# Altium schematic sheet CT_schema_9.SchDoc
size 226 x 144 mm
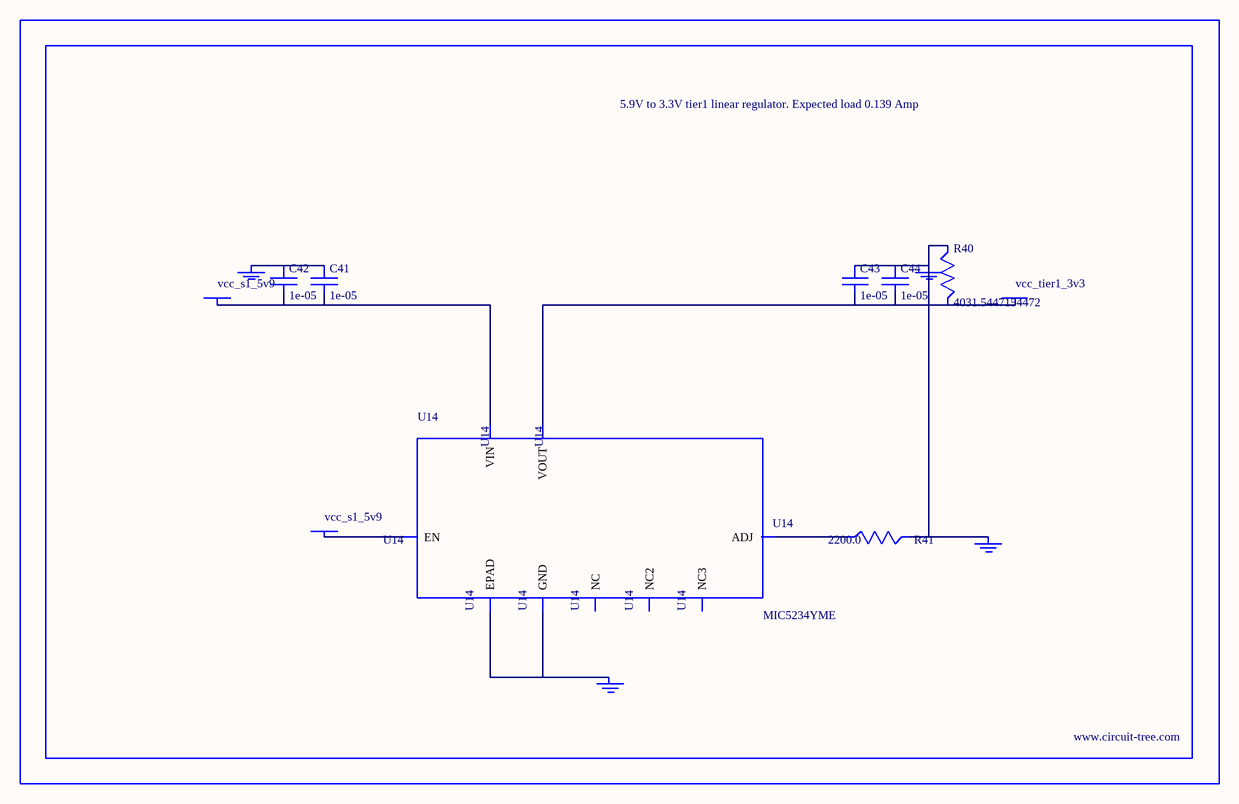
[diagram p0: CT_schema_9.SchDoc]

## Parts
BORDER8  (no value)
C41  1e-05  [C1210]
C42  1e-05  [C1210]
C43  1e-05  [C1210]
C44  1e-05  [C1210]
GND_INSTANCE_8_0  (no value)
GND_INSTANCE_8_1  (no value)
GND_INSTANCE_8_2  (no value)
GND_INSTANCE_8_3  (no value)
POWER_INSTANCE_8_0  vcc_tier1_3v3
POWER_INSTANCE_8_1  vcc_s1_5v9
POWER_INSTANCE_8_2  vcc_s1_5v9
R40  4031.5447154472  [R0603]
R41  2200.0  [R0603]
U14  MIC5234YME  [SOIC-8_EP]

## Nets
NetC41_1: C41.1 C42.1 GND_INSTANCE_8_3.0(GND)
NetC41_2: C41.2 C42.2 POWER_INSTANCE_8_2.0(PWR) U14.8(VIN)
NetC43_1: C43.1 C44.1 GND_INSTANCE_8_0.0(GND) GND_INSTANCE_8_1.0(GND) R40.1 R41.2
NetC43_2: C43.2 C44.2 POWER_INSTANCE_8_0.0(PWR) R40.2 U14.1(VOUT)
NetGND_INSTANCE_8_2_0: GND_INSTANCE_8_2.0(GND) U14.7(GND) U14.EPAD
NetPOWER_INSTANCE_8_1_0: POWER_INSTANCE_8_1.0(PWR) U14.5(EN)
NetR41_1: R41.1 U14.4(ADJ)

Not connected (* = marked no-connect by the designer): U14 2(NC) 3(NC2) 6(NC3)

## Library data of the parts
BORDER8 = BORDER_PAGE8
C41-C44 = C1210C106K5PACTU
GND_INSTANCE_8_0-GND_INSTANCE_8_3 = GND
POWER_INSTANCE_8_0-POWER_INSTANCE_8_2 = PWR
R40 = R40
R41 = RC0603JR-072K2L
